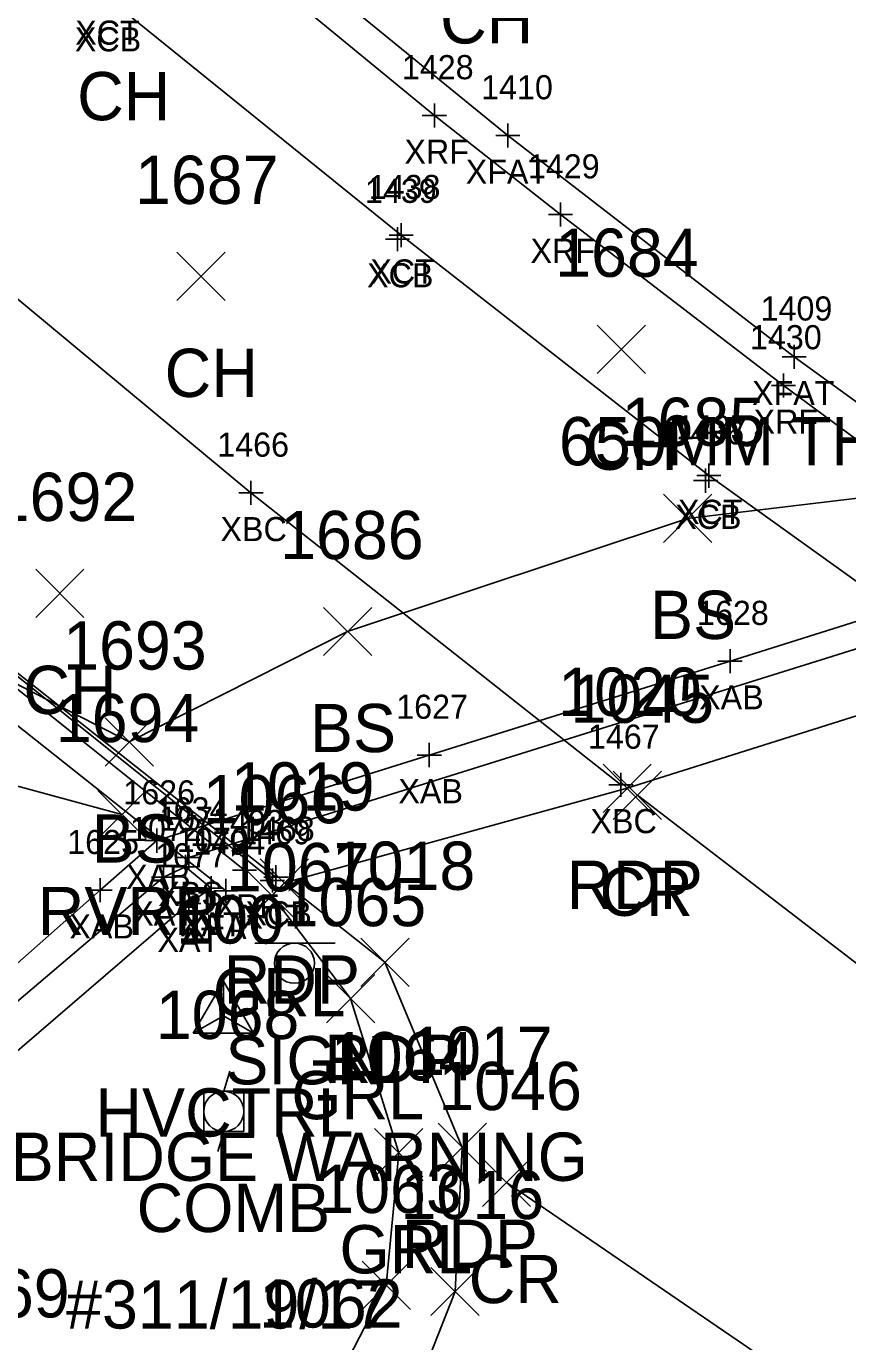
# Model space of a CAD drawing. Extents: x 1616726 to 1619875, y 273782 to 276557.
# Drawn here: x 1617021.7 to 1617055.8, y 276211.4 to 276265.9 of the extents above; entities that cross this region are included whole.
import ezdxf

# ---------------------------------------------------------------- set-up
doc = ezdxf.new("R2010")
doc.units = 0
for name, color, linetype in [('B_A', 7, 'Continuous'), ('B_C', 7, 'Continuous'), ('B_I', 7, 'Continuous'), ('B_TIC', 7, 'Continuous'), ('BDC', 7, 'Continuous'), ('BELB', 7, 'Continuous'), ('BF', 7, 'Continuous'), ('BR', 7, 'Continuous'), ('BSE', 7, 'Continuous'), ('BSUBM', 7, 'Continuous'), ('C_A', 7, 'Continuous'), ('C_I', 7, 'Continuous'), ('CPSM', 7, 'Continuous'), ('L_A', 7, 'Continuous'), ('L_I', 7, 'Continuous'), ('L_TIC', 7, 'Continuous'), ('LAWE', 7, 'Continuous'), ('LELB', 7, 'Continuous'), ('P_A', 7, 'Continuous'), ('P_I', 7, 'Continuous'), ('P_TIC', 7, 'Continuous'), ('PET', 7, 'Continuous'), ('PRC', 7, 'Continuous'), ('R_A', 7, 'Continuous'), ('R_I', 7, 'Continuous'), ('R_TIC', 7, 'Continuous'), ('RGR', 7, 'Continuous'), ('S_A', 7, 'Continuous'), ('S_C', 7, 'Continuous'), ('S_I', 7, 'Continuous'), ('SSGN', 7, 'Continuous'), ('U_A', 7, 'Continuous'), ('U_C', 7, 'Continuous'), ('U_I', 7, 'Continuous'), ('UP', 7, 'Continuous')]:
    doc.layers.add(name, color=color, linetype=linetype)

msp = doc.modelspace()

# ---------------------------------------------------------------- linework, layer by layer
at = {"layer": 'B_TIC'}
for p, q in [((1617038.656, 276262.201), (1617038.732, 276262.201)), ((1617041.701, 276261.369), (1617041.776, 276261.369)), ((1617043.883, 276258.091), (1617043.958, 276258.091)), ((1617037.132, 276257.077), (1617037.207, 276257.077)), ((1617037.283, 276257.235), (1617037.359, 276257.235)), ((1617053.567, 276252.2), (1617053.643, 276252.2)), ((1617053.128, 276251.01), (1617053.204, 276251.01)), ((1617049.901, 276247.066), (1617049.976, 276247.066)), ((1617050.034, 276247.273), (1617050.109, 276247.273)), ((1617031.056, 276246.557), (1617031.132, 276246.557)), ((1617050.912, 276239.585), (1617050.988, 276239.585)), ((1617038.446, 276235.694), (1617038.522, 276235.694)), ((1617046.392, 276234.455), (1617046.467, 276234.455)), ((1617027.161, 276232.146), (1617027.236, 276232.146)), ((1617028.477, 276231.443), (1617028.553, 276231.443)), ((1617027.429, 276230.625), (1617027.504, 276230.625)), ((1617028.35, 276231.06), (1617028.425, 276231.06)), ((1617030.788, 276230.919), (1617030.863, 276230.919)), ((1617032.092, 276230.634), (1617032.168, 276230.634)), ((1617024.81, 276230.09), (1617024.885, 276230.09)), ((1617029.41, 276230.18), (1617029.485, 276230.18)), ((1617030.016, 276230.064), (1617030.092, 276230.064)), ((1617031.943, 276230.493), (1617032.019, 276230.493)), ((1617028.475, 276229.537), (1617028.55, 276229.537))]:
    msp.add_line(p, q, dxfattribs=at)
for points in [[(1617038.153, 276262.201), (1617039.153, 276262.201)], [(1617038.653, 276261.701), (1617038.653, 276262.701)], [(1617041.697, 276260.869), (1617041.697, 276261.869)], [(1617041.197, 276261.369), (1617042.197, 276261.369)], [(1617043.879, 276257.591), (1617043.879, 276258.591)], [(1617043.379, 276258.091), (1617044.379, 276258.091)], [(1617037.128, 276256.577), (1617037.128, 276257.577)], [(1617037.28, 276256.735), (1617037.28, 276257.735)], [(1617036.628, 276257.077), (1617037.628, 276257.077)], [(1617036.78, 276257.235), (1617037.78, 276257.235)], [(1617053.564, 276251.7), (1617053.564, 276252.7)], [(1617053.064, 276252.2), (1617054.064, 276252.2)], [(1617053.125, 276250.51), (1617053.125, 276251.51)], [(1617052.625, 276251.01), (1617053.625, 276251.01)], [(1617049.897, 276246.566), (1617049.897, 276247.566)], [(1617050.03, 276246.773), (1617050.03, 276247.773)], [(1617031.053, 276246.057), (1617031.053, 276247.057)], [(1617049.397, 276247.066), (1617050.397, 276247.066)], [(1617049.53, 276247.273), (1617050.53, 276247.273)], [(1617030.553, 276246.557), (1617031.553, 276246.557)], [(1617050.909, 276239.085), (1617050.909, 276240.085)], [(1617050.409, 276239.585), (1617051.409, 276239.585)], [(1617038.443, 276235.194), (1617038.443, 276236.194)], [(1617037.943, 276235.694), (1617038.943, 276235.694)], [(1617046.388, 276233.955), (1617046.388, 276234.955)], [(1617045.888, 276234.455), (1617046.888, 276234.455)], [(1617027.157, 276231.646), (1617027.157, 276232.646)], [(1617026.657, 276232.146), (1617027.657, 276232.146)], [(1617028.474, 276230.943), (1617028.474, 276231.943)], [(1617027.425, 276230.125), (1617027.425, 276231.125)], [(1617027.974, 276231.443), (1617028.974, 276231.443)], [(1617028.346, 276230.56), (1617028.346, 276231.56)], [(1617030.784, 276230.419), (1617030.784, 276231.419)], [(1617032.089, 276230.134), (1617032.089, 276231.134)], [(1617024.806, 276229.59), (1617024.806, 276230.59)], [(1617026.925, 276230.625), (1617027.925, 276230.625)], [(1617027.846, 276231.06), (1617028.846, 276231.06)], [(1617029.406, 276229.68), (1617029.406, 276230.68)], [(1617030.013, 276229.564), (1617030.013, 276230.564)], [(1617030.284, 276230.919), (1617031.284, 276230.919)], [(1617031.589, 276230.634), (1617032.589, 276230.634)], [(1617031.94, 276229.993), (1617031.94, 276230.993)], [(1617024.306, 276230.09), (1617025.306, 276230.09)], [(1617028.471, 276229.037), (1617028.471, 276230.037)], [(1617028.906, 276230.18), (1617029.906, 276230.18)], [(1617029.513, 276230.064), (1617030.513, 276230.064)], [(1617031.44, 276230.493), (1617032.44, 276230.493)], [(1617027.971, 276229.537), (1617028.971, 276229.537)]]:
    msp.add_lwpolyline(points, dxfattribs=at)
at = {"layer": 'BDC'}
for points in [[(1617066.201, 276240.881), (1617061.118, 276239.32), (1617050.03, 276247.273), (1617037.28, 276257.235), (1617025.05, 276267.134), (1617011.056, 276279.412), (1616998.482, 276291.126), (1616985.44, 276304.157), (1616972.744, 276317.666), (1616966.897, 276324.299), (1616966.458, 276325.419), (1616970.937, 276326.925)], [(1617031.94, 276230.493), (1617019.04, 276240.812), (1617003.309, 276253.921), (1616987.272, 276268.372), (1616971.94, 276283.404), (1616957.293, 276298.592), (1616946.104, 276311.237), (1616940.906, 276317.316)], [(1617032.089, 276230.634), (1617019.011, 276240.957), (1617003.449, 276254.007), (1616987.219, 276268.519), (1616972.153, 276283.37), (1616957.519, 276298.646), (1616946.38, 276311.131), (1616940.99, 276317.433)]]:
    msp.add_lwpolyline(points, dxfattribs=at)
at = {"layer": 'BELB'}
msp.add_lwpolyline([(1616953.623, 276321.315), (1616970.875, 276302.028), (1616987.05, 276285.607), (1616997.927, 276275.138), (1617015.409, 276259.543), (1617031.053, 276246.557), (1617046.388, 276234.455)], dxfattribs=at)
at = {"layer": 'BF'}
for points in [[(1617068.317, 276241.506), (1617053.564, 276252.2), (1617041.697, 276261.369), (1617028.541, 276272.109), (1617018.019, 276281.339), (1617008.62, 276289.852), (1616999.219, 276298.836), (1616985.651, 276312.733), (1616977.318, 276321.612), (1616972.286, 276327.269)], [(1617030.013, 276230.064), (1617015.816, 276241.312), (1617001.537, 276253.314), (1616989.849, 276263.729), (1616982.397, 276270.726), (1616969.932, 276282.988), (1616958.21, 276295.373), (1616947.149, 276307.449), (1616939.121, 276316.789)]]:
    msp.add_lwpolyline(points, dxfattribs=at)
at = {"layer": 'BR'}
for points in [[(1616971.054, 276326.754), (1616977.692, 276319.392), (1616984.666, 276311.834), (1616992.708, 276303.608), (1616998.498, 276297.74), (1617007.24, 276289.498), (1617013.196, 276284.039), (1617021.735, 276276.403), (1617028.158, 276270.837), (1617038.653, 276262.201), (1617043.879, 276258.091), (1617053.125, 276251.01), (1617059.814, 276246.064), (1617066.819, 276241.017)], [(1616940.542, 276317.169), (1616949.786, 276306.506), (1616958.097, 276297.283), (1616966.707, 276288.28), (1616975.45, 276279.333), (1616984.398, 276270.583), (1616994.032, 276261.605), (1617003.798, 276253.031), (1617019.439, 276239.958), (1617030.784, 276230.919)]]:
    msp.add_lwpolyline(points, dxfattribs=at)
at = {"layer": 'BSE'}
msp.add_lwpolyline([(1617066.488, 276243.332), (1617028.474, 276231.443)], dxfattribs=at)
at = {"layer": 'BSUBM'}
for points in [[(1617010.577, 276214.426), (1617009.604, 276215.712), (1617012.165, 276218.528), (1617020.162, 276225.998), (1617024.806, 276230.09), (1617027.157, 276232.146), (1617038.443, 276235.694), (1617050.909, 276239.585), (1617068.456, 276245.114), (1617089.814, 276247.416), (1617090.344, 276244.994)], [(1617029.406, 276230.18), (1617028.346, 276231.06), (1617027.425, 276230.625), (1617018.564, 276223.108), (1617009.875, 276215.569), (1617010.866, 276214.533), (1617018.799, 276221.224), (1617028.471, 276229.537)], [(1617028.471, 276229.537), (1617029.406, 276230.18)]]:
    msp.add_lwpolyline(points, dxfattribs=at)
at = {"layer": 'CPSM'}
for p, q in [((1617028.663, 276224.16), (1617029.913, 276226.325)), ((1617028.663, 276224.16), (1617029.913, 276226.325)), ((1617028.663, 276224.16), (1617029.913, 276226.325)), ((1617031.163, 276224.16), (1617029.913, 276226.325)), ((1617029.914, 276224.881), (1617029.913, 276226.325)), ((1617031.163, 276224.16), (1617029.913, 276226.325)), ((1617029.914, 276224.881), (1617029.913, 276226.325)), ((1617031.163, 276224.16), (1617029.913, 276226.325)), ((1617029.914, 276224.881), (1617029.913, 276226.325)), ((1617028.663, 276224.16), (1617029.914, 276224.881)), ((1617028.663, 276224.16), (1617029.914, 276224.881)), ((1617028.663, 276224.16), (1617029.914, 276224.881)), ((1617029.914, 276224.881), (1617029.914, 276224.881)), ((1617029.914, 276224.881), (1617031.163, 276224.16)), ((1617029.914, 276224.881), (1617029.914, 276224.881)), ((1617029.914, 276224.881), (1617031.163, 276224.16)), ((1617029.914, 276224.881), (1617029.914, 276224.881)), ((1617029.914, 276224.881), (1617031.163, 276224.16)), ((1617028.663, 276224.16), (1617031.163, 276224.16)), ((1617028.663, 276224.16), (1617031.163, 276224.16)), ((1617028.663, 276224.16), (1617031.163, 276224.16))]:
    msp.add_line(p, q, dxfattribs=at)
at = {"layer": 'L_TIC'}
for points in [[(1617027.986, 276254.532), (1617029.986, 276256.532)], [(1617029.986, 276254.532), (1617027.986, 276256.532)], [(1617045.401, 276251.512), (1617047.401, 276253.512)], [(1617047.401, 276251.512), (1617045.401, 276253.512)], [(1617048.151, 276244.503), (1617050.151, 276246.503)], [(1617050.151, 276244.503), (1617048.151, 276246.503)], [(1617022.131, 276241.393), (1617024.131, 276243.393)], [(1617024.131, 276241.393), (1617022.131, 276243.393)], [(1617034.056, 276239.813), (1617036.056, 276241.813)], [(1617036.056, 276239.813), (1617034.056, 276241.813)], [(1617025.009, 276235.235), (1617027.009, 276237.235)], [(1617027.009, 276235.235), (1617025.009, 276237.235)], [(1617024.704, 276232.229), (1617026.704, 276234.229)], [(1617026.704, 276232.229), (1617024.704, 276234.229)]]:
    msp.add_lwpolyline(points, dxfattribs=at)
at = {"layer": 'LAWE'}
msp.add_lwpolyline([(1617025.704, 276233.229), (1617015.623, 276235.97), (1617001.802, 276236.481), (1616993.715, 276237.76), (1616982.576, 276237.202), (1616969.982, 276238.819), (1616958.412, 276240.145), (1616941.628, 276245.844), (1616918.276, 276250.862), (1616897.517, 276255.185), (1616867.227, 276263.214), (1616844.351, 276269.714), (1616814.421, 276281.911), (1616791.447, 276293.204)], dxfattribs=at)
at = {"layer": 'LELB'}
msp.add_lwpolyline([(1617180.325, 276288.326), (1617161.431, 276281.848), (1617137.104, 276278.445), (1617120.409, 276268.034), (1617108.303, 276262.949), (1617094.244, 276258.017), (1617079.483, 276248.101), (1617068.225, 276247.781), (1617049.151, 276245.503), (1617035.056, 276240.813), (1617026.009, 276236.235), (1617014.974, 276241.9), (1616972.474, 276247.818), (1616960.605, 276245.765), (1616944.032, 276250.468), (1616920.652, 276257.271), (1616898.689, 276263.021), (1616845.503, 276278.094), (1616816.834, 276290.556), (1616792.378, 276296.226)], dxfattribs=at)
at = {"layer": 'P_TIC'}
for points in [[(1617045.645, 276233.316), (1617047.645, 276235.316)], [(1617047.645, 276233.316), (1617045.645, 276235.316)], [(1617046.068, 276233.028), (1617048.068, 276235.028)], [(1617048.068, 276233.028), (1617046.068, 276235.028)], [(1617031.436, 276229.391), (1617033.436, 276231.391)], [(1617033.436, 276229.391), (1617031.436, 276231.391)], [(1617035.606, 276226.106), (1617037.606, 276228.106)], [(1617037.606, 276226.106), (1617035.606, 276228.106)], [(1617038.812, 276218.435), (1617040.812, 276220.435)], [(1617040.812, 276218.435), (1617038.812, 276220.435)], [(1617040.645, 276216.977), (1617042.645, 276218.977)], [(1617042.645, 276216.977), (1617040.645, 276218.977)], [(1617038.512, 276212.461), (1617040.512, 276214.461)], [(1617040.512, 276212.461), (1617038.512, 276214.461)]]:
    msp.add_lwpolyline(points, dxfattribs=at)
at = {"layer": 'PET'}
msp.add_lwpolyline([(1616989.426, 276201.185), (1617018.474, 276198.311), (1617030.262, 276200.676), (1617036.67, 276206.238), (1617039.512, 276213.461), (1617039.812, 276219.435), (1617036.606, 276227.106), (1617032.436, 276230.391), (1617046.645, 276234.316), (1617061.092, 276238.884), (1617067.899, 276234.233), (1617072.399, 276230.992), (1617088.603, 276220.185), (1617112.483, 276205), (1617131.155, 276194.642), (1617156.357, 276182.31), (1617186.295, 276169.867), (1617215.497, 276159.966), (1617247.442, 276151.441), (1617259.727, 276148.347), (1617264.103, 276152.292), (1617286.332, 276147.086), (1617304.444, 276145.412), (1617352.203, 276136.042)], dxfattribs=at)
at = {"layer": 'PRC'}
for points in [[(1617347.132, 276116.475), (1617295.92, 276126.996), (1617256.555, 276135.984), (1617216.872, 276146.76), (1617173.085, 276161.717), (1617139.463, 276175.956), (1617104.94, 276194.234), (1617079.375, 276210.711), (1617058.932, 276224.92), (1617047.068, 276234.028)], [(1617041.645, 276217.977), (1617061.285, 276204.546), (1617083.936, 276188.349), (1617106.492, 276174.288), (1617135.311, 276159.982)]]:
    msp.add_lwpolyline(points, dxfattribs=at)
at = {"layer": 'R_TIC'}
for points in [[(1617030.926, 276228.864), (1617032.926, 276230.864)], [(1617032.926, 276228.864), (1617030.926, 276230.864)], [(1617034.182, 276224.601), (1617036.182, 276226.601)], [(1617036.182, 276224.601), (1617034.182, 276226.601)], [(1617036.178, 276218.211), (1617038.178, 276220.211)], [(1617038.178, 276218.211), (1617036.178, 276220.211)], [(1617035.662, 276212.714), (1617037.662, 276214.714)], [(1617037.662, 276212.714), (1617035.662, 276214.714)]]:
    msp.add_lwpolyline(points, dxfattribs=at)
at = {"layer": 'RGR'}
msp.add_lwpolyline([(1617009.982, 276205.685), (1617016.328, 276202.513), (1617023.331, 276201.809), (1617029.923, 276204.485), (1617034.206, 276208.967), (1617036.662, 276213.714), (1617037.178, 276219.211), (1617035.182, 276225.601), (1617031.926, 276229.864)], dxfattribs=at)
at = {"layer": 'SSGN'}
for p, q in [((1617031.208, 276227.899), (1617034.541, 276227.899)), ((1617032.855, 276227.065), (1617032.855, 276227.065))]:
    msp.add_line(p, q, dxfattribs=at)
msp.add_circle((1617032.855, 276227.065), 0.833, dxfattribs=at)
at = {"layer": 'UP'}
for p, q in [((1617030.177, 276222.592), (1617029.927, 276221.758)), ((1617029.094, 276220.092), (1617029.094, 276221.758)), ((1617029.094, 276221.758), (1617030.76, 276221.758)), ((1617030.76, 276221.758), (1617030.76, 276220.092)), ((1617029.927, 276220.925), (1617029.927, 276220.925)), ((1617030.76, 276220.092), (1617029.094, 276220.092)), ((1617029.677, 276219.258), (1617029.927, 276220.092))]:
    msp.add_line(p, q, dxfattribs=at)
msp.add_circle((1617029.927, 276220.925), 0.833, dxfattribs=at)

# ---------------------------------------------------------------- texts
at = {"layer": 'B_A'}
for s, p in [('XCT', (1617023.77, 276265.134)), ('XCB', (1617023.753, 276264.853)), ('XRF', (1617037.413, 276260.201)), ('XFAT', (1617039.953, 276259.369)), ('XRF', (1617042.639, 276256.091)), ('XCT', (1617036, 276255.235)), ('XCB', (1617035.864, 276255.077)), ('XFAT', (1617051.82, 276250.2)), ('XRF', (1617051.885, 276249.01)), ('XCB', (1617048.634, 276245.066)), ('XCT', (1617048.751, 276245.273)), ('XBC', (1617029.789, 276244.557)), ('XAB', (1617049.629, 276237.585)), ('XAB', (1617037.163, 276233.694)), ('XBC', (1617045.124, 276232.455)), ('XAB', (1617025.878, 276230.146)), ('XAT', (1617027.051, 276229.06)), ('XBS', (1617027.214, 276229.443)), ('XAT', (1617026.13, 276228.625)), ('XRF', (1617029.544, 276228.919)), ('XCT', (1617030.66, 276228.493)), ('XCB', (1617030.825, 276228.634)), ('XAB', (1617023.527, 276228.09)), ('XAT', (1617028.111, 276228.18)), ('XFAT', (1617028.269, 276228.064)), ('XAT', (1617027.176, 276227.537))]:
    msp.add_text(s, height=1, dxfattribs=at).set_placement(p)
at = {"layer": 'B_C'}
msp.add_text('650MM THICK', height=2, dxfattribs=at).set_placement((1617043.816, 276247.7))
at = {"layer": 'B_I'}
for s, p in [('1428', (1617037.306, 276263.701)), ('1410', (1617040.591, 276262.869)), ('1429', (1617042.529, 276259.591)), ('1439', (1617035.778, 276258.577)), ('1438', (1617035.933, 276258.735)), ('1409', (1617052.174, 276253.7)), ('1430', (1617051.735, 276252.51)), ('1437', (1617048.684, 276248.773)), ('1436', (1617048.523, 276248.566)), ('1466', (1617029.655, 276248.057)), ('1628', (1617049.539, 276241.085)), ('1627', (1617037.073, 276237.194)), ('1467', (1617045.018, 276235.955)), ('1626', (1617025.76, 276233.646)), ('1634', (1617027.104, 276232.943)), ('1071', (1617027.244, 276232.56)), ('1493', (1617029.438, 276232.419)), ('1072', (1617026.039, 276232.125)), ('1469', (1617030.566, 276231.993)), ('1468', (1617030.719, 276232.134)), ('1625', (1617023.436, 276231.59)), ('1070', (1617027.977, 276231.68)), ('1494', (1617028.666, 276231.564)), ('1077', (1617027.085, 276231.037))]:
    msp.add_text(s, height=1, dxfattribs=at).set_placement(p)
at = {"layer": 'C_A'}
msp.add_text('HVCTRL', height=2, dxfattribs=at).set_placement((1617024.607, 276219.881))
msp.add_text('HVCTRL', height=2, dxfattribs=at).set_placement((1617024.607, 276219.881))
msp.add_text('HVCTRL', height=2, dxfattribs=at).set_placement((1617024.607, 276219.881))
at = {"layer": 'C_I'}
msp.add_text('100', height=2, dxfattribs=at).set_placement((1617027.953, 276227.881))
msp.add_text('100', height=2, dxfattribs=at).set_placement((1617027.953, 276227.881))
msp.add_text('100', height=2, dxfattribs=at).set_placement((1617027.953, 276227.881))
at = {"layer": 'L_A'}
for s, p in [('CH', (1617038.894, 276265.182)), ('CH', (1617023.849, 276262)), ('CH', (1617027.474, 276250.532)), ('CH', (1617044.89, 276247.512)), ('BS', (1617047.592, 276240.503)), ('CH', (1617021.62, 276237.393)), ('BS', (1617033.497, 276235.813)), ('BS', (1617024.45, 276231.235)), ('RVRR', (1617022.216, 276228.229))]:
    msp.add_text(s, height=2, dxfattribs=at).set_placement(p)
at = {"layer": 'L_I'}
for s, p in [('1687', (1617026.246, 276258.532)), ('1684', (1617043.661, 276255.512)), ('1685', (1617046.411, 276248.503)), ('1692', (1617020.391, 276245.393)), ('1686', (1617032.261, 276243.813)), ('1693', (1617023.269, 276239.235)), ('1694', (1617022.964, 276236.229)), ('1069', (1617017.587, 276212.385))]:
    msp.add_text(s, height=2, dxfattribs=at).set_placement(p)
at = {"layer": 'P_A'}
for s, p in [('RDP', (1617044.134, 276229.316)), ('CR', (1617045.501, 276229.028)), ('RDP', (1617029.924, 276225.391)), ('RDP', (1617034.094, 276222.106)), ('RDP', (1617037.3, 276214.435)), ('CR', (1617040.078, 276212.977))]:
    msp.add_text(s, height=2, dxfattribs=at).set_placement(p)
at = {"layer": 'P_I'}
for s, p in [('1020', (1617043.787, 276237.316)), ('1045', (1617044.296, 276237.028)), ('1019', (1617030.223, 276233.391)), ('1018', (1617034.401, 276230.106)), ('1017', (1617037.607, 276222.435)), ('1046', (1617038.818, 276220.977)), ('1016', (1617037.252, 276216.461))]:
    msp.add_text(s, height=2, dxfattribs=at).set_placement(p)
at = {"layer": 'R_A'}
for p in [(1617029.47, 276224.864), (1617032.726, 276220.601), (1617034.721, 276214.211)]:
    msp.add_text('GRL', height=2, dxfattribs=at).set_placement(p)
at = {"layer": 'R_I'}
for s, p in [('1066', (1617029.052, 276232.864)), ('1065', (1617032.364, 276228.601)), ('1064', (1617034.359, 276222.211)), ('1063', (1617033.843, 276216.714)), ('1062', (1617031.387, 276211.967))]:
    msp.add_text(s, height=2, dxfattribs=at).set_placement(p)
at = {"layer": 'S_A'}
msp.add_text('SIGN', height=2, dxfattribs=at).set_placement((1617029.993, 276222.045))
at = {"layer": 'S_C'}
msp.add_text('BRIDGE WARNING', height=2, dxfattribs=at).set_placement((1617021.095, 276218.045))
at = {"layer": 'S_I'}
msp.add_text('1067', height=2, dxfattribs=at).set_placement((1617030.016, 276230.045))
at = {"layer": 'U_A'}
msp.add_text('COMB', height=2, dxfattribs=at).set_placement((1617026.313, 276215.925))
at = {"layer": 'U_C'}
msp.add_text('#311/19/17', height=2, dxfattribs=at).set_placement((1617023.391, 276211.925))
at = {"layer": 'U_I'}
msp.add_text('1068', height=2, dxfattribs=at).set_placement((1617027.108, 276223.925))

doc.saveas('drawing.dxf')
